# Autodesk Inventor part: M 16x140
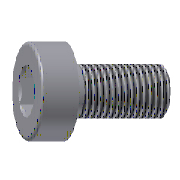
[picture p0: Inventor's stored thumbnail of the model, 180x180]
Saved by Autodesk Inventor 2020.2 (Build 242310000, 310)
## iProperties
Manager: www.cadconsulting.pl
Company: Fabian Stasiak CAD Consulting
Created: 2014-02
Part Number: M 16x140
Material: Stal, miękka
Description: Socket Head Cap Screw DIN 912 - 12.9
Document SubType Name: Modeling
Designer: F.Stasiak
Standard Revision: 1
Manufacturer: DME
Language: pl-PL
Size Designation: 16x140
Categories: <MemberInstance><Categories><Category DisplayName="Forma wtryskowa" InternalName="349578f2-f4d4-4954-8c09-8e99297a61c0" Mnemonic="MOLD"><Category DisplayName="C
Mass: 0.133121 g
Surface Area: 2.01441 cm^2
Volume: 0.133121 cm^3
Density: 7.85 g/cm^3
Appearance: Częściowo polerowana
Catalog Web Link: www.expertbooks.pl
IsCustomPart: 0
Author: F.Stasiak
Subject: Zbiór ćwiczeń. Autodesk Inventor 2020. Kurs Professional
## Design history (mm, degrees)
sketch "Sketch1"
  geometry: L1 (0, -171.2)-(0, 47.2) reference; L2 (8.083, 16)-(12, 16); L3 (12, 16)-(12, 0); L4 (12, 0)-(8, 0); L5 (8, 0)-(8, -140); L6 (8, -140)-(0, -140); L7 (0, 3.794)-(0, -140); L8 (0, 3.794)-(7, 8); L9 (7, 8)-(7, 14.917); L10 (7, 14.917)-(8.083, 16); 1 further point
  constraints: 18 end point, 4 vertical, 3 horizontal, 2 point on line
  dimensions: "d0" = 24 diameter of L3 L1 (= dk); "d1" = 16 distance between parallel lines of L4 L2 (= k); "d2" = 16 diameter of L5 L1 (= d); "d3" = 140 distance between parallel lines of L6 L4 (= L); "d4" = 59 deg angle of L1 L8; "d5" = 45 deg angle of L1 L10; "d6" = 14 diameter of L9 L1 (= sw); "d7" = 16.16581 diameter of L2.start L1 (= 1.1547 x sw); "d8" = 8 distance from line of L8.end L2 (= t)
revolve "Revolution1" sketch "Sketch1" stored, may be unused: angle "d44" = 90 deg
sketch "Sketch2"
  geometry: L1 (0, 8.083)-(7, 4.041); L2 (7, 4.041)-(7, -4.041); L3 (7, -4.041)-(0, -8.083); L4 (0, -8.083)-(-7, -4.041); L5 (-7, -4.041)-(-7, 4.041); L6 (-7, 4.041)-(0, 8.083); 3 further points
  constraints: 12 end point, 2 vertical alignment, 1 coincident, 14 other
extrude "Extrusion1" cut sketch "Sketch2" taper "d9" = 0 deg; stored distance "d45" = 10
thread "Thread1" dims "d10" = 44 (= b), "d11" = 0
chamfer "Chamfer1" distance "d12" = 1 (= 0.5 x P); stored, may be unused: second distance "d50" = 2, angle "d51" = 45 deg
fillet "Fillet1" dims "d13" = 1 (= 0.5 x P)
body "Solid1"
other parameters: "d" = 16 [user parameter; used in 1 equation term], "L" = 140 [user parameter; used in 1 equation term], "dk" = 24 [user parameter; used in 1 equation term], "b" = 44 [user parameter; used in 1 equation term], "k" = 16 [user parameter; used in 1 equation term], "sw" = 14 [user parameter; used in 2 equation terms], "t" = 8 [user parameter; used in 1 equation term], "P" = 2 [user parameter; used in 2 equation terms], "d14" = 0, "d15" = 0, "d55" = 0
